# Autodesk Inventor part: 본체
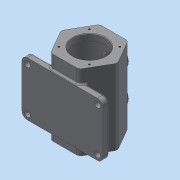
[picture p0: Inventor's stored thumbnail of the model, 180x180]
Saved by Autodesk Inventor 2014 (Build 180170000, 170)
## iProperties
Created: 2021-06
Part Number: 본체
Material: 일반
Document SubType Name: Modeling
Designer: net
Density: 1 g/cm^3
Appearance: 기본값
Author: net
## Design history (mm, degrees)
sketch "스케치1" dims "d0" = 105
  geometry: L1 (-52.5, 0)-(-26.25, 45.466); L2 (-26.25, 45.466)-(26.25, 45.466); L3 (26.25, 45.466)-(52.5, 0); L4 (52.5, 0)-(26.25, -45.466); L5 (26.25, -45.466)-(-26.25, -45.466); L6 (-26.25, -45.466)-(-52.5, 0); 3 further points
  constraints: 12 end point, 2 coincident, 1 horizontal alignment, 15 other
  dimensions: "d1" = 45.46633 vertical distance of L2.end L3.end
extrude "돌출1" new body sketch "스케치1" distance "d2" = 140; taper "d3" = 0 deg
node "작업 평면1"
sketch "스케치2"
  geometry: L1 (-52.5, 0)-(-26.25, 45.466) reference; L2 (-26.25, 45.466)-(26.25, 45.466) reference; L3 (26.25, 45.466)-(52.5, 0) reference; L4 (52.5, 0)-(26.25, -45.466) reference; L5 (26.25, -45.466)-(-26.25, -45.466) reference; L6 (-26.25, -45.466)-(-52.5, 0) reference; L7 (-75, -50)-(75, -50); L8 (75, -50)-(75, -38); L9 (75, -38)-(-75, -38); L10 (-75, -38)-(-75, -50); 2 further points
  constraints: 8 end point, 2 parallel, 1 horizontal, 1 midpoint, 1 perpendicular, 1 vertical alignment
  dimensions: "d5" = 12 distance of L7.end L8.end; "d6" = 50 distance from line of L7 point (0, 0); "d7" = 150 distance of L7.start L7.end
extrude "돌출2" join sketch "스케치2" distance "d8" = 100; taper "d9" = 0 deg
node "작업 평면2"
sketch "스케치3"
  geometry: L1 (0, 12)-(0, 4.534) reference; L2 (0, 4.534)-(-25, 4.534) reference; L3 (-25, 50)-(-25, 4.534) reference; L4 (115, 50)-(-25, 50) reference; L5 (115, 4.534)-(115, 50) reference; L6 (115, 4.534)-(100, 4.534) reference; L7 (100, 4.534)-(100, 12) reference; L8 (100, 12)-(0, 12) reference; L9 (115, 50)-(115, 95.466) reference; L10 (115, 50)-(-25, 50) reference; L11 (-25, 95.466)-(-25, 50) reference; L12 (115, 95.466)-(-25, 95.466) reference; L13 (-25, 50)-(115, 50); L14 (-25, 50)-(-25, 80); L15 (-25, 80)-(-13, 80); L16 (-13, 80)-(-13, 87.5); L17 (-13, 87.5)-(103, 87.5); L18 (103, 87.5)-(103, 80); L19 (103, 80)-(115, 80); L20 (115, 50)-(115, 80); 1 further point
  constraints: 16 end point, 3 perpendicular, 3 point on line, 1 collinear, 1 parallel
  dimensions: "d10" = 12 distance of L14.end L15.end; "d11" = 12 distance of L18.end L19.end; "d12" = 60 diameter of L19 L4; "d13" = 60 diameter of L15 L4; "d14" = 75 diameter of L17 L4
revolve "회전1" sketch "스케치3" stored, may be unused: angle "d15" = 90 deg
chamfer "모따기1" distance "d16" = 1; stored, may be unused: second distance "d17" = 2, angle "d18" = 45 deg
fillet "모깎기1" dims "d19" = 5
fillet "모깎기2" dims "d20" = 5
sketch "스케치4"
  geometry: L1 (52.5, -140)-(0, -140) reference; 4 further points
  constraints: 2 vertical alignment, 1 midpoint
  dimensions: "d21" = 40 distance from line of L1 point (26.25, -100); "d22" = 60 distance of point (26.25, -40) point (26.25, -100)
hole "구멍1" sketch "스케치4" at (26.25, -100), (26.25, -40) diameter "d23" = 25; stored, may be unused: countersink angle "d27" = 90 deg, drill point angle "d29" = 0 deg; dims "d24" = 6, "d25" = 4, "d26" = 2, "d28" = 10
node "작업 평면3"
sketch "스케치5"
  geometry: L1 (26.25, 0)-(-26.25, 0) reference; L2 (26.25, 0)-(26.25, 140) reference; L3 (-26.25, 140)-(26.25, 140) reference; L4 (-26.25, 0)-(-26.25, 140) reference; C1 r 12.5 at (0, 100) reference; C2 r 12.5 at (0, 40) reference; C3 r 20 at (0, 100); C4 r 20 at (0, 40); 1 further point
  constraints: 2 centre point, 2 coincident, 1 equal radius
  dimensions: "d31" = 40 diameter of C3
extrude "돌출3" join sketch "스케치5" stored distance "d32" = 100; taper "d33" = 0 deg
sketch "스케치6"
  geometry: C1 r 12.5 at (0, 0) reference; C2 r 12.5 at (0, 60) reference; C3 r 20 at (0, 60) reference; 1 further point
hole "구멍2" sketch "스케치6" at (0, 0), (0, 60) diameter "d34" = 30; stored, may be unused: countersink angle "d38" = 90 deg, drill point angle "d40" = 0 deg; dims "d35" = 6, "d36" = 4, "d37" = 2, "d39" = 8
fillet "모깎기3" dims "d41" = 10
sketch "스케치7"
  geometry: L1 (105.561, 10)-(105.561, 90) reference; L2 (61.121, 100)-(95.561, 100) reference; L3 (61.121, 0)-(61.121, 100) reference; L4 (95.561, 0)-(61.121, 0) reference; A1 r 10 centre (-34.439, 10) between (-44.439, 10) and (-34.439, 0) reference; A2 r 10 centre (-34.439, 90) between (-34.439, 100) and (-44.439, 90) reference; A3 r 10 centre (95.561, 10) between (95.561, 0) and (105.561, 10) reference; A4 r 10 centre (95.561, 90) between (105.561, 90) and (95.561, 100) reference; 1 further point
hole "구멍3" sketch "스케치7" at (-34.439, 10), (-34.439, 90), (95.561, 90), (95.561, 10) diameter "d42" = 11; stored, may be unused: countersink angle "d46" = 90 deg, drill point angle "d48" = 0 deg; dims "d43" = 6, "d44" = 4, "d45" = 2, "d47" = 8
sketch "스케치8"
  geometry: L1 (0, 0)-(-34.439, 0) reference; L2 (-44.439, 10)-(-44.439, 90) reference; 2 further points
  constraints: 1 other
  dimensions: "d49" = 50 distance from line of L1 point (-30.439, 50); "d50" = 14 distance from line of point (-30.439, 50) L2
extrude "돌출4" join sketch "스케치8" distance "d51" = 0.5; taper "d52" = 0 deg
fillet "모깎기4" dims "d53" = 3
fillet "모깎기5" dims "d54" = 8
fillet "모깎기6" dims "d55" = 3
fillet "모깎기7" dims "d56" = 3
node "작업 평면4"
sketch "스케치10"
  geometry: L1 (21.631, 45.466)-(-21.631, 45.466) reference; L2 (0, 0)-(0, 40); L3 (0, 0)-(-28.284, 28.284); C1 r 31 at (0, 0) reference; A1 r 40 centre (0, 0) between (0, 40) and (-28.284, 28.284); 1 further point
  constraints: 4 end point, 2 coincident, 2 point on circle, 1 centre point, 1 perpendicular
  dimensions: "d69" = 80 diameter of A1; "d70" = 45 deg angle of L3 L2
hole "구멍5" sketch "스케치10" at (-28.284, 28.284) diameter "d71" = 3.242; stored, may be unused: countersink angle "d75" = 90 deg, drill point angle "d77" = 118 deg; dims "d72" = 8, "d73" = 4, "d74" = 2, "d76" = 10
sketch "스케치11" dims "d81" = 80
  geometry: C1 r 31 at (0, 0) reference; 2 further points
  constraints: 2 vertical alignment, 1 coincident, 2 other
hole "구멍6" sketch "스케치11" at (0, 40) diameter "d82" = 3.242; stored, may be unused: countersink angle "d86" = 90 deg, drill point angle "d88" = 118 deg; dims "d83" = 8, "d84" = 4, "d85" = 2, "d87" = 10
chamfer "모따기2" distance "d92" = 1; stored, may be unused: second distance "d93" = 2, angle "d94" = 45 deg
node "솔리드1"
pattern_circular "원형 패턴2" dims angle "d79" = 360 deg
pattern_circular "원형 패턴3" dims angle "d90" = 360 deg
node "투영된 루프1"
node "투영된 루프2"
node "투영된 루프3"
node "투영된 루프4"
node "투영된 루프5"
node "투영된 루프6"
other parameters: "d4" = -25, "d30" = 52.5
